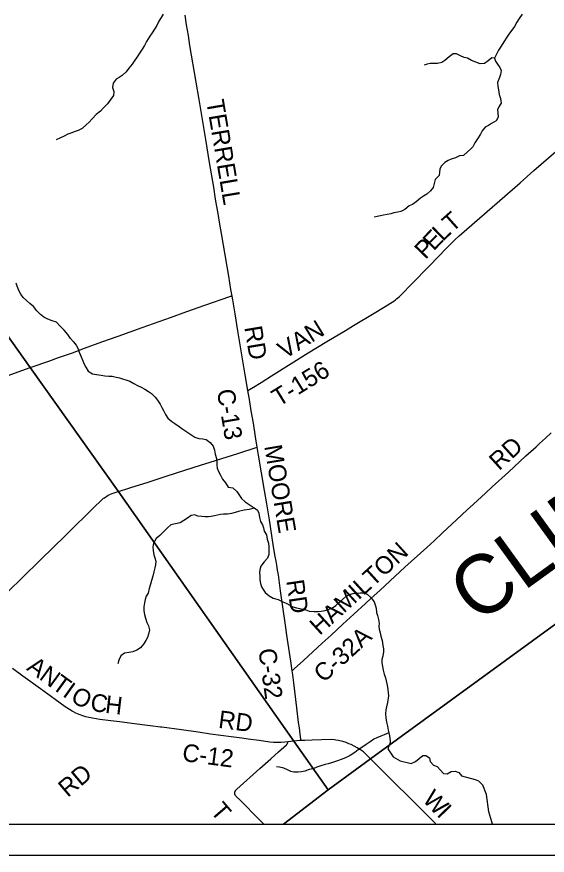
# Model space of a CAD drawing. Extents: x 0 to 34, y 0 to 22.
# Drawn here: x 3.164 to 4.871, y 14 to 16.697 of the extents above; entities that cross this region are included whole.
import ezdxf

# ---------------------------------------------------------------- set-up
doc = ezdxf.new("R2010")
doc.units = 0
for name, color, linetype in [('Default', 7, 'Continuous'), ('GM_X_County_Road', 7, 'Continuous'), ('GM_X_County_Road_Text', 7, 'Continuous'), ('GM_X_County_Text', 7, 'Continuous'), ('GM_X_Minor_River', 7, 'Continuous'), ('GM_X_Township_Road', 7, 'Continuous'), ('GM_X_Township_Road_Text', 7, 'Continuous'), ('SH_Cut_Line', 7, 'Continuous'), ('SH_Data', 7, 'Continuous')]:
    doc.layers.add(name, color=color, linetype=linetype)

msp = doc.modelspace()

# ---------------------------------------------------------------- linework, layer by layer
at = {"layer": 'Default'}
msp.add_lwpolyline([(6.6858, 19.0362), (6.6949, 19.1537), (6.8302, 20.9), (3.1229, 20.9), (2.9275, 20.8467), (2.2946, 20.6707), (2.1, 20.6202), (2.1, 17.1279), (2.1211, 17.1003), (3.2076, 15.5689), (3.4902, 15.1704), (4.0558, 14.3671), (4.1658, 14.2105), (4.302, 14.3105), (5.6165, 15.2674), (6.0871, 15.6176), (6.2834, 15.7529), (6.4392, 15.8657), (6.5428, 17.1931), (6.5451, 17.2211), (6.6309, 18.3364), (6.6363, 18.3979), (6.6654, 18.7733)], dxfattribs=at)
for points in [[(2.1, 17.1279), (2.1, 14.1), (4.022, 14.1), (4.1658, 14.2105), (4.0558, 14.3671), (3.4902, 15.1704), (3.2076, 15.5689), (2.1211, 17.1003)], [(4.022, 14.1), (8.9, 14.1), (8.9, 15.8067), (8.1324, 15.8252), (7.3679, 15.8435), (6.5786, 15.8624), (6.4392, 15.8657), (6.2834, 15.7529), (6.0871, 15.6176), (5.6165, 15.2674), (4.302, 14.3105), (4.1658, 14.2105)]]:
    msp.add_lwpolyline(points, close=True, dxfattribs=at)
at = {"layer": 'GM_X_County_Road'}
msp.add_line((4.056, 14.3666), (4.0362, 14.3646), dxfattribs=at)
for points in [[(3.8568, 15.7986), (3.8533, 15.8193), (3.846, 15.8628), (3.8227, 15.9994), (3.8177, 16.0294), (3.8118, 16.0643), (3.808, 16.0864), (3.804, 16.1102), (3.7977, 16.1489), (3.7845, 16.2279), (3.7724, 16.3015), (3.7596, 16.3787), (3.7509, 16.4302), (3.7415, 16.4859), (3.7215, 16.6042), (3.7163, 16.6367), (3.7107, 16.671), (3.7056, 16.7017)], [(3.9077, 15.4945), (3.8993, 15.5448), (3.8753, 15.6863), (3.8665, 15.7409), (3.859, 15.7862), (3.8568, 15.7986)], [(3.9379, 15.3123), (3.9325, 15.3456), (3.9254, 15.3891), (3.9185, 15.4295), (3.9125, 15.4657), (3.9077, 15.4945)], [(4.0502, 14.5932), (4.0568, 14.5993), (4.0864, 14.6267), (4.1469, 14.682), (4.1752, 14.7081), (4.2133, 14.7429), (4.2481, 14.7748), (4.2865, 14.8101), (4.3034, 14.8258), (4.3332, 14.853), (4.4128, 14.9261), (4.483, 14.9901), (4.5065, 15.0114), (4.5338, 15.0368), (4.5789, 15.0786), (4.6135, 15.1107), (4.6333, 15.1287), (4.6716, 15.1641), (4.6939, 15.1848), (4.7455, 15.2324), (4.8023, 15.2845), (4.8346, 15.3136), (4.8456, 15.3237), (4.8652, 15.3418), (4.8834, 15.3587)], [(3.4904, 15.1699), (3.4951, 15.1713), (3.5212, 15.1794), (3.5343, 15.1836), (3.5834, 15.1991), (3.6444, 15.2187), (3.7047, 15.238), (3.7556, 15.2542), (3.7859, 15.2637), (3.8238, 15.2757), (3.8756, 15.2923), (3.9379, 15.3123)], [(4.0502, 14.5932), (4.0456, 14.6239), (4.0334, 14.7075), (4.0286, 14.7401), (4.0131, 14.8502), (4.0058, 14.9023), (4.0052, 14.9061), (4.0049, 14.9085), (4.0045, 14.9109), (4.0009, 14.9331), (3.9985, 14.9459), (3.9957, 14.9612), (3.9905, 14.9924), (3.9771, 15.0783), (3.9686, 15.1298), (3.9613, 15.1733), (3.9424, 15.2867), (3.9379, 15.3123)], [(3.1393, 14.8507), (3.1805, 14.8912), (3.2409, 14.9503), (3.3207, 15.0287), (3.417, 15.1231), (3.4328, 15.1382), (3.4365, 15.1416), (3.4438, 15.1479), (3.4466, 15.15), (3.4507, 15.153), (3.4538, 15.155), (3.4584, 15.1576), (3.4634, 15.1601), (3.4663, 15.1614), (3.4709, 15.1633), (3.4774, 15.1656), (3.4904, 15.1699)], [(3.6264, 14.4122), (3.5935, 14.4162), (3.5349, 14.4239), (3.4955, 14.4291), (3.4671, 14.4327), (3.432, 14.437), (3.4081, 14.4404), (3.3959, 14.4428), (3.3863, 14.4451), (3.3763, 14.4483), (3.3653, 14.4524), (3.3539, 14.4573), (3.3468, 14.4609), (3.3423, 14.4634), (3.3339, 14.4684), (3.3201, 14.4778), (3.2879, 14.5011), (3.2404, 14.5351), (3.1841, 14.576), (3.1503, 14.6003)], [(4.0783, 14.3687), (4.0777, 14.374), (4.0758, 14.3898), (4.0733, 14.4095), (4.071, 14.4274), (4.0655, 14.4743), (4.0556, 14.5545), (4.0522, 14.5797), (4.0502, 14.5932)], [(4.0362, 14.3646), (4.027, 14.3636), (4.0146, 14.3626), (4.0109, 14.3624), (4.0046, 14.3623), (4.0005, 14.3623), (3.9941, 14.3626), (3.9905, 14.3628), (3.9783, 14.3641), (3.9438, 14.3687), (3.9087, 14.3738), (3.8884, 14.3764), (3.854, 14.3812), (3.7874, 14.3898), (3.7474, 14.3954), (3.6945, 14.4028), (3.6311, 14.4116), (3.6264, 14.4122)], [(4.0783, 14.3687), (4.0753, 14.3685), (4.056, 14.3666)], [(4.3022, 14.31), (4.2798, 14.3323), (4.2699, 14.3386), (4.2592, 14.3455), (4.2492, 14.3511), (4.2398, 14.3557), (4.2322, 14.3588), (4.2235, 14.3621), (4.213, 14.3656), (4.1995, 14.3687), (4.1911, 14.3703), (4.1861, 14.3709), (4.1759, 14.3721), (4.1442, 14.3711), (4.1144, 14.3701), (4.0907, 14.3694), (4.0841, 14.3691), (4.0783, 14.3687)], [(4.5126, 14.1), (4.5107, 14.1019), (4.4766, 14.1359), (4.4222, 14.1909), (4.3835, 14.2288), (4.3293, 14.2829), (4.3022, 14.31)]]:
    msp.add_lwpolyline(points, dxfattribs=at)
at = {"layer": 'GM_X_Minor_River'}
for points in [[(3.635, 16.7053), (3.6291, 16.6939), (3.6214, 16.6822), (3.6147, 16.669), (3.607, 16.6569), (3.5996, 16.6445), (3.5926, 16.6339), (3.5818, 16.6173), (3.5748, 16.6041), (3.5678, 16.5924), (3.5616, 16.5826), (3.5519, 16.5675), (3.5418, 16.554), (3.5352, 16.5442), (3.5248, 16.5314), (3.5167, 16.5197), (3.5036, 16.5073), (3.4936, 16.5017), (3.4841, 16.4965), (3.4748, 16.4829)], [(4.79, 16.7046), (4.7807, 16.6906), (4.7731, 16.6789), (4.765, 16.6657), (4.7565, 16.6536), (4.7492, 16.6438), (4.7412, 16.6313), (4.7315, 16.6162), (4.7227, 16.6018), (4.7139, 16.5894), (4.7081, 16.5788), (4.7015, 16.564), (4.7045, 16.5534), (4.7105, 16.5439), (4.718, 16.5335), (4.7221, 16.524), (4.7208, 16.5111), (4.7169, 16.5009), (4.7111, 16.4858), (4.7122, 16.4725), (4.714, 16.4615), (4.7161, 16.447), (4.7202, 16.4341), (4.7228, 16.4192), (4.7155, 16.4094), (4.7104, 16.3969), (4.7122, 16.3874), (4.7133, 16.3738), (4.7063, 16.3624), (4.6915, 16.3534), (4.6819, 16.3474), (4.6705, 16.3414), (4.6613, 16.3294), (4.6559, 16.3195), (4.6459, 16.3044), (4.6378, 16.2912), (4.6309, 16.2783), (4.6234, 16.2705)], [(4.627, 16.5565), (4.6141, 16.5635), (4.6038, 16.5659), (4.5917, 16.571), (4.5785, 16.5776), (4.5682, 16.5773), (4.5551, 16.5676), (4.5417, 16.556), (4.5317, 16.5496), (4.5176, 16.546), (4.5073, 16.5469), (4.494, 16.5459), (4.4845, 16.5441), (4.4745, 16.5408)], [(4.7016, 16.5637), (4.6924, 16.5641), (4.6802, 16.5551), (4.6683, 16.5464), (4.6546, 16.5454), (4.6414, 16.5504), (4.627, 16.5565)], [(3.4748, 16.4829), (3.4723, 16.4693), (3.4763, 16.4567), (3.4758, 16.4438), (3.4669, 16.4313), (3.4561, 16.4167), (3.4426, 16.4027), (3.4333, 16.393), (3.4199, 16.3821), (3.4072, 16.3686), (3.3972, 16.3577), (3.3875, 16.3494), (3.3748, 16.3378), (3.3618, 16.3311), (3.3519, 16.3274), (3.3385, 16.3226), (3.329, 16.3186), (3.3167, 16.3122), (3.3049, 16.3074), (3.2911, 16.3007)], [(4.6234, 16.2705), (4.6142, 16.2619), (4.6008, 16.251), (4.5886, 16.2489), (4.5752, 16.243), (4.5618, 16.2385), (4.5515, 16.2341), (4.5408, 16.2281), (4.5292, 16.2161), (4.5253, 16.2063), (4.524, 16.1964), (4.5227, 16.1858), (4.5104, 16.173), (4.5072, 16.1609), (4.504, 16.1476), (4.4955, 16.1367), (4.4828, 16.1262), (4.4721, 16.1195), (4.4625, 16.1135), (4.4494, 16.1015), (4.4368, 16.0926), (4.4265, 16.0881), (4.4126, 16.0769), (4.3996, 16.0702), (4.3901, 16.068), (4.3775, 16.0662), (4.3679, 16.0633), (4.3554, 16.0612), (4.3439, 16.059), (4.334, 16.0565), (4.3241, 16.0543), (4.3142, 16.0525)], [(3.3471, 15.6515), (3.337, 15.6624), (3.3288, 15.675), (3.3164, 15.6884), (3.3032, 15.7023), (3.2923, 15.7142), (3.2783, 15.7189), (3.2639, 15.7236), (3.2511, 15.731), (3.2405, 15.7394), (3.2293, 15.7514), (3.218, 15.7648), (3.2067, 15.774), (3.1958, 15.784), (3.1853, 15.794), (3.1774, 15.8044), (3.1711, 15.8166), (3.1655, 15.83), (3.1622, 15.8395)], [(3.3471, 15.6515), (3.3549, 15.6404), (3.3616, 15.6282), (3.3649, 15.6183), (3.3712, 15.6034), (3.3772, 15.5901), (3.3816, 15.5794), (3.3861, 15.5695), (3.3936, 15.5573), (3.4079, 15.548), (3.4208, 15.5457), (3.4356, 15.544), (3.4477, 15.5416), (3.4606, 15.5404), (3.4716, 15.5403), (3.4845, 15.5379), (3.4943, 15.5355), (3.5042, 15.5324), (3.5182, 15.5281), (3.528, 15.5242), (3.5408, 15.5169), (3.5525, 15.5111), (3.5642, 15.5049), (3.5767, 15.4987), (3.5884, 15.4914), (3.5982, 15.4848), (3.6095, 15.4733), (3.617, 15.4638), (3.626, 15.4508), (3.6308, 15.4405), (3.6364, 15.4302), (3.6427, 15.4176), (3.6506, 15.4054), (3.663, 15.3954), (3.6728, 15.3881), (3.6868, 15.3789), (3.6981, 15.3701), (3.7113, 15.3616), (3.7245, 15.3535), (3.7366, 15.345), (3.7502, 15.34), (3.7631, 15.3387), (3.7737, 15.3367), (3.7869, 15.3275), (3.7959, 15.3153), (3.7999, 15.3031), (3.8028, 15.2902), (3.8073, 15.2757), (3.8083, 15.2658), (3.8082, 15.256), (3.8089, 15.2453), (3.8144, 15.232), (3.8201, 15.2221), (3.826, 15.2099), (3.8358, 15.1973), (3.8447, 15.1835), (3.8595, 15.1815), (3.8727, 15.1696), (3.8783, 15.1601), (3.8873, 15.1471), (3.899, 15.1371), (3.9114, 15.1275), (3.9246, 15.1198), (3.9382, 15.1094), (3.9434, 15.0999), (3.9455, 15.0858), (3.9481, 15.0729), (3.9544, 15.0622), (3.9578, 15.0527), (3.9603, 15.0424), (3.9674, 15.0302), (3.97, 15.0165), (3.974, 15.004), (3.9747, 14.9914), (3.9746, 14.9816), (3.9748, 14.9675), (3.9709, 14.9558), (3.9606, 14.9437), (3.9494, 14.9294), (3.9459, 14.9177), (3.9451, 14.9082), (3.9457, 14.8987), (3.9464, 14.8862), (3.9478, 14.8736), (3.9519, 14.8637), (3.9567, 14.8542), (3.9638, 14.8446), (3.9763, 14.8339), (3.9891, 14.8269), (4.0046, 14.823), (4.0201, 14.8149), (4.0307, 14.8103), (4.0424, 14.8048), (4.0522, 14.799), (4.0636, 14.7952), (4.0749, 14.7931), (4.0946, 14.7892), (4.1052, 14.7853), (4.1196, 14.7844), (4.1336, 14.7843), (4.1439, 14.7846)], [(3.9294, 15.1161), (3.912, 15.1123), (3.8961, 15.1098), (3.8774, 15.105), (3.8671, 15.1021), (3.855, 15.0988), (3.8417, 15.097), (3.8295, 15.0971), (3.82, 15.0964), (3.8098, 15.0939), (3.7999, 15.0913), (3.79, 15.0891), (3.7805, 15.0881), (3.7703, 15.0885), (3.7597, 15.0894), (3.7471, 15.091), (3.7373, 15.0945), (3.7248, 15.0924), (3.7137, 15.0845), (3.7022, 15.077), (3.6897, 15.0692), (3.6744, 15.0659), (3.6604, 15.0626), (3.65, 15.0536), (3.6374, 15.0415), (3.6248, 15.0284), (3.6122, 15.0186), (3.6037, 15.0035), (3.602, 14.9903), (3.6027, 14.9804), (3.6056, 14.9663), (3.6089, 14.9568), (3.6119, 14.9454), (3.611, 14.9344), (3.6083, 14.9242), (3.6047, 14.912), (3.6016, 14.8973), (3.598, 14.884), (3.5945, 14.8723), (3.5906, 14.8579), (3.5867, 14.8431), (3.5809, 14.8329), (3.5778, 14.8227), (3.575, 14.8121), (3.5726, 14.7992), (3.5729, 14.7863), (3.575, 14.7738), (3.5787, 14.7624), (3.5831, 14.749), (3.5876, 14.7376), (3.5909, 14.7254), (3.5881, 14.7114), (3.5846, 14.7008), (3.5792, 14.691), (3.5723, 14.6793), (3.5627, 14.6669), (3.5501, 14.6598), (3.5379, 14.6538), (3.525, 14.6516), (3.5109, 14.6495), (3.4991, 14.6409), (3.4921, 14.6269), (3.4897, 14.6155)], [(4.1439, 14.7846), (4.1564, 14.7871), (4.1675, 14.7908), (4.18, 14.7956), (4.1911, 14.8035), (4.2018, 14.8133), (4.2114, 14.8211), (4.2236, 14.8328), (4.2351, 14.8388), (4.2461, 14.8417), (4.2567, 14.8431), (4.2685, 14.8441), (4.2795, 14.8437), (4.2912, 14.8398), (4.3029, 14.8287), (4.3138, 14.8153), (4.3167, 14.805), (4.32, 14.7947), (4.3218, 14.7807), (4.3244, 14.7708), (4.3277, 14.7586), (4.3298, 14.7457), (4.329, 14.7362), (4.33, 14.7267), (4.3337, 14.7149), (4.3359, 14.7042), (4.3396, 14.6905), (4.3417, 14.675), (4.3439, 14.6643), (4.3438, 14.6545), (4.3418, 14.6404), (4.339, 14.6294), (4.3386, 14.6188), (4.3411, 14.6067), (4.3433, 14.5952), (4.3458, 14.5827), (4.3499, 14.5705), (4.3524, 14.5606), (4.3557, 14.5469), (4.3579, 14.5332), (4.3593, 14.5222), (4.3603, 14.5124), (4.3564, 14.4908), (4.3532, 14.4771), (4.3516, 14.4673), (4.3507, 14.4547), (4.351, 14.4422), (4.3531, 14.4282), (4.3568, 14.4152), (4.3593, 14.4023), (4.3626, 14.3894), (4.3644, 14.3772), (4.3658, 14.3662), (4.3657, 14.3621)], [(4.3615, 14.3937), (4.3459, 14.3872), (4.3349, 14.3828), (4.3227, 14.378), (4.3124, 14.3735), (4.301, 14.3652), (4.2884, 14.3566), (4.2738, 14.3465), (4.262, 14.3387), (4.2513, 14.3308), (4.2364, 14.321), (4.2216, 14.3128), (4.2079, 14.308), (4.1964, 14.304), (4.1763, 14.2969), (4.1656, 14.294), (4.1561, 14.2918), (4.1428, 14.2877), (4.1298, 14.2829), (4.118, 14.2781), (4.1047, 14.2756), (4.091, 14.2707), (4.0804, 14.2678), (4.069, 14.2668), (4.0557, 14.2673), (4.0455, 14.2693), (4.0353, 14.2747), (4.0236, 14.2801), (4.0096, 14.2833), (4.0001, 14.2841)], [(4.3657, 14.3621), (4.3577, 14.3418), (4.3747, 14.3169), (4.398, 14.3033), (4.4328, 14.2948), (4.4465, 14.301), (4.4703, 14.3203), (4.4798, 14.3206), (4.4915, 14.3136), (4.4943, 14.3014), (4.5044, 14.2898), (4.5168, 14.2855), (4.5373, 14.2624), (4.5483, 14.2622), (4.5617, 14.2689), (4.5742, 14.2706), (4.5859, 14.2662), (4.5959, 14.2539)], [(4.6944, 14.1), (4.6929, 14.1079), (4.6824, 14.1392), (4.6749, 14.1948), (4.6635, 14.225), (4.6504, 14.2377), (4.6398, 14.2421), (4.5959, 14.2539)]]:
    msp.add_lwpolyline(points, dxfattribs=at)
at = {"layer": 'GM_X_Township_Road'}
for points in [[(3.9077, 15.4945), (3.9132, 15.4979), (3.9254, 15.5053), (3.9501, 15.5209), (3.9837, 15.5422), (4.102, 15.6154), (4.1619, 15.6521), (4.2215, 15.688), (4.2476, 15.7037), (4.3134, 15.7437), (4.3498, 15.7652), (4.3669, 15.7754), (4.372, 15.7788), (4.3773, 15.7822), (4.3822, 15.786), (4.3862, 15.789), (4.3902, 15.7925), (4.3951, 15.7967), (4.3984, 15.7999), (4.4012, 15.8027), (4.4049, 15.8063), (4.4323, 15.8342), (4.4932, 15.8972), (4.5457, 15.9511), (4.5618, 15.9675), (4.5739, 15.9791), (4.5876, 15.9917), (4.7585, 16.1408), (4.784, 16.1627), (4.828, 16.202), (4.8986, 16.2638)], [(3.2078, 15.5684), (3.2143, 15.5707), (3.2676, 15.5895), (3.2987, 15.6003), (3.3432, 15.6162), (3.3822, 15.6305), (3.4377, 15.6508), (3.4903, 15.6697), (3.5676, 15.697), (3.6589, 15.7296), (3.7115, 15.7485), (3.7688, 15.7691), (3.8498, 15.7975), (3.8513, 15.7978), (3.8535, 15.7981), (3.8568, 15.7986)], [(3.1336, 15.5419), (3.2078, 15.5684)], [(3.9593, 14.1), (3.9452, 14.1143), (3.8814, 14.1777), (3.8715, 14.1877), (3.87, 14.1893), (3.8688, 14.1907), (3.8681, 14.1917), (3.8674, 14.1928), (3.8669, 14.1935), (3.8663, 14.1946), (3.8659, 14.1955), (3.8657, 14.1961), (3.8655, 14.197), (3.8654, 14.198), (3.8653, 14.1992), (3.8653, 14.2), (3.8656, 14.2023), (3.8658, 14.2032), (3.8662, 14.2042), (3.8666, 14.2051), (3.8671, 14.2061), (3.8675, 14.2067), (3.8683, 14.2079), (3.8691, 14.209), (3.8703, 14.2104), (3.8712, 14.2113), (3.8726, 14.2126), (3.9459, 14.2785), (3.9814, 14.3103), (4.0063, 14.3325), (4.0236, 14.3479), (4.0321, 14.3555), (4.0327, 14.356), (4.0334, 14.3568), (4.0339, 14.3574), (4.0345, 14.3583), (4.035, 14.3593), (4.0353, 14.36), (4.0356, 14.3609), (4.0359, 14.3618), (4.0361, 14.3631), (4.0361, 14.3639), (4.0362, 14.3646)]]:
    msp.add_lwpolyline(points, dxfattribs=at)
at = {"layer": 'SH_Cut_Line'}
msp.add_lwpolyline([(6.6858, 19.0362), (6.6949, 19.1537), (6.8302, 20.9), (2.1, 20.9), (2.1, 14.1), (4.022, 14.1), (4.1658, 14.2105), (4.302, 14.3105), (5.6165, 15.2674), (6.0871, 15.6176), (6.2834, 15.7529), (6.4392, 15.8657), (6.5428, 17.1931), (6.5451, 17.2211), (6.6309, 18.3364), (6.6363, 18.3979), (6.6654, 18.7733)], dxfattribs=at)
at = {"layer": 'SH_Data'}
for p, q in [((2.1, 14.1), (8.9, 14.1)), ((2, 14), (9, 14))]:
    msp.add_line(p, q, dxfattribs=at)

# ---------------------------------------------------------------- texts
at = {"layer": 'GM_X_County_Road_Text'}
for s, height, rotation, p in [('TERRELL', 0.05682, 279.5655, (3.7736, 16.4255)), ('RD', 0.05682, 279.463, (3.8961, 15.698)), ('C-13', 0.05682, 279.6319, (3.8074, 15.4948)), ('MOORE', 0.05682, 279.5245, (3.9601, 15.3157)), ('RD', 0.05682, 42.2075, (4.7156, 15.2351)), ('HAMILTON', 0.05682, 42.4629, (4.1387, 14.705)), ('RD', 0.05682, 278.4101, (4.031, 14.8827)), ('C-32A', 0.05682, 42.526, (4.1514, 14.5525)), ('C-32', 0.05682, 278.037, (3.9411, 14.6616)), ('A', 0.0568, 324.0109, (3.1929, 14.5975)), ('N', 0.0568, 324.0118, (3.2333, 14.5681)), ('T', 0.0568, 324.0694, (3.2738, 14.5387)), ('I', 0.0568, 324.5832, (3.3087, 14.5135)), ('O', 0.0568, 331.5807, (3.3342, 14.4959)), ('C', 0.0568, 351.4663, (3.3985, 14.4653)), ('H', 0.0568, 353.2332, (3.4465, 14.4582)), ('RD', 0.05682, 352.5688, (3.8106, 14.4099)), ('C-12', 0.05682, 352.4006, (3.6943, 14.3035)), ('W', 0.0568, 314.0208, (4.4667, 14.1764)), ('I', 0.0568, 314.0235, (4.5125, 14.1291))]:
    msp.add_text(s, height=height, rotation=rotation, dxfattribs=at).set_placement(p)
at = {"layer": 'GM_X_County_Text'}
msp.add_text('CLINTON COUNTY', height=0.189394, rotation=35.9139, dxfattribs=at).set_placement((4.6459, 14.7404))
at = {"layer": 'GM_X_Township_Road_Text'}
for s, height, rotation, p in [('T', 0.0568, 41.5979, (4.5644, 16.0011)), ('L', 0.0568, 44.3333, (4.5345, 15.9719)), ('E', 0.0568, 45.9243, (4.5052, 15.9417)), ('P', 0.0568, 46.0551, (4.4787, 15.9141)), ('VAN', 0.05682, 31.6691, (4.0263, 15.5943)), ('T-156', 0.05682, 31.5888, (4.0072, 15.4413)), ('RD', 0.05682, 40.1786, (3.3279, 14.184)), ('T', 0.0568, 310.6715, (3.7846, 14.1399))]:
    msp.add_text(s, height=height, rotation=rotation, dxfattribs=at).set_placement(p)

doc.saveas('drawing.dxf')
